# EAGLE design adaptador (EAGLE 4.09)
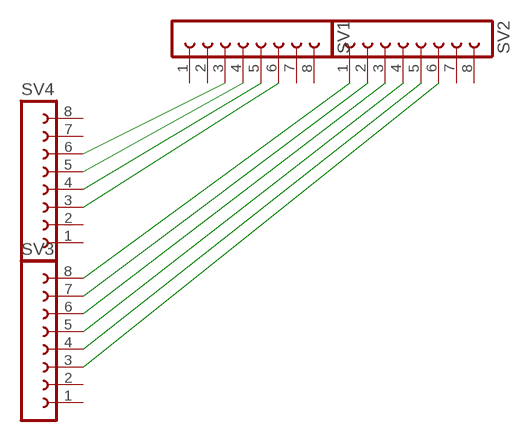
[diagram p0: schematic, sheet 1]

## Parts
SV1  FE08-1  [FE08]
SV2  FE08-1  [FE08]
SV3  FE08-1  [FE08]
SV4  FE08-1  [FE08]

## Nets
N$3: SV1.3 SV4.6
N$4: SV1.4 SV4.5
N$5: SV1.5 SV4.4
N$6: SV1.6 SV4.3
N$9: SV2.1 SV3.8
N$10: SV2.2 SV3.7
N$11: SV2.3 SV3.6
N$12: SV2.4 SV3.5
N$13: SV2.5 SV3.4
N$14: SV2.6 SV3.3
Unconnected: SV1.1 SV1.2 SV1.7 SV1.8 SV2.7 SV2.8 SV3.1 SV3.2 SV4.1 SV4.2 SV4.7 SV4.8

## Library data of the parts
SV1-SV4 = con-lsta:FE08-1: FEMALE HEADER

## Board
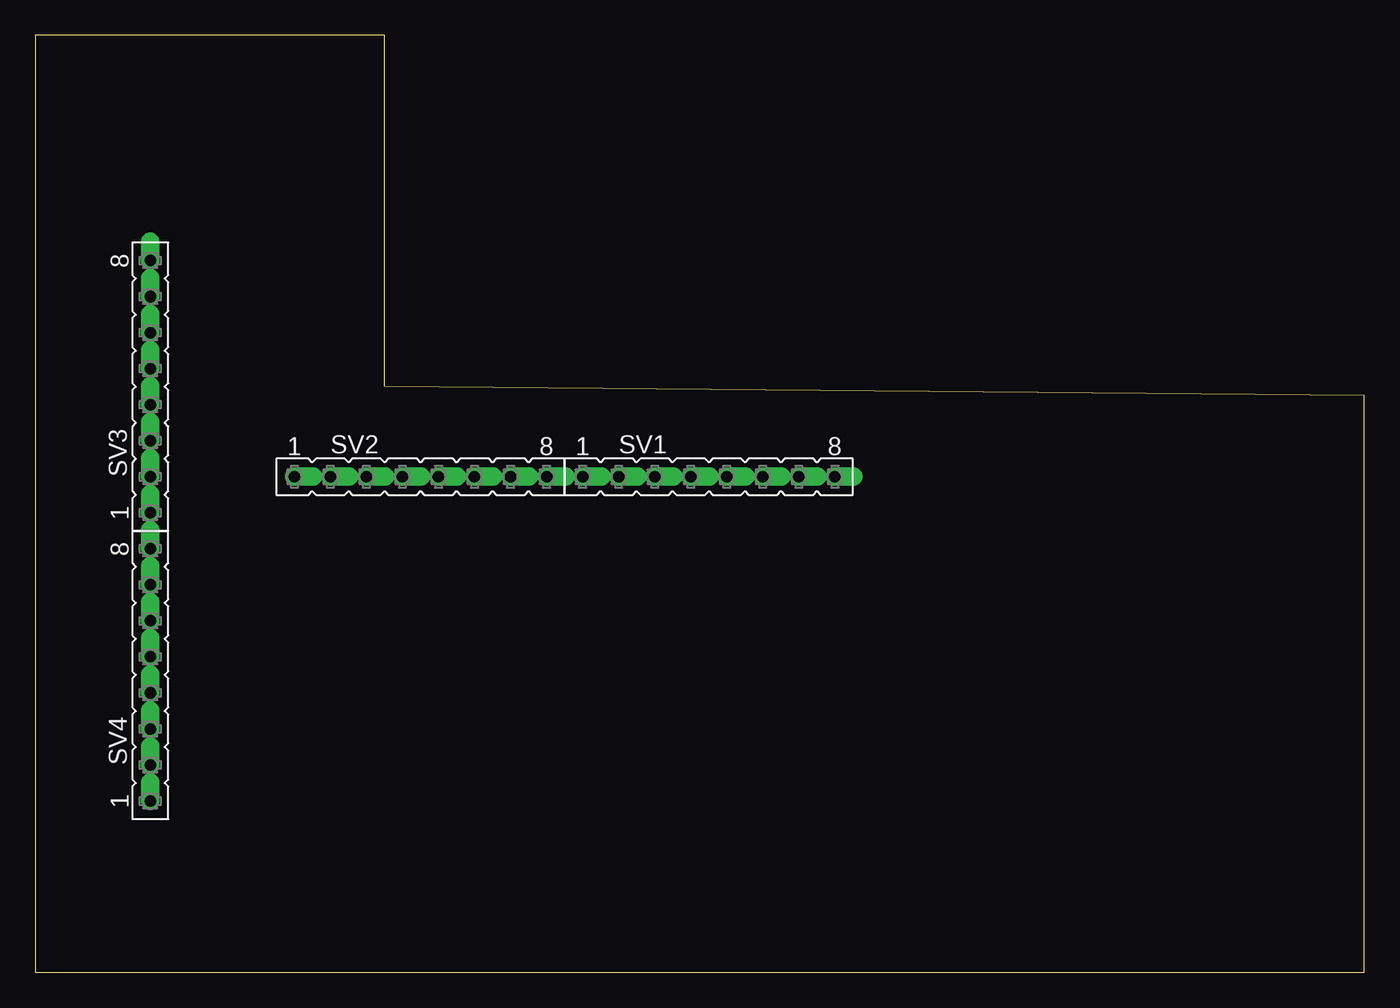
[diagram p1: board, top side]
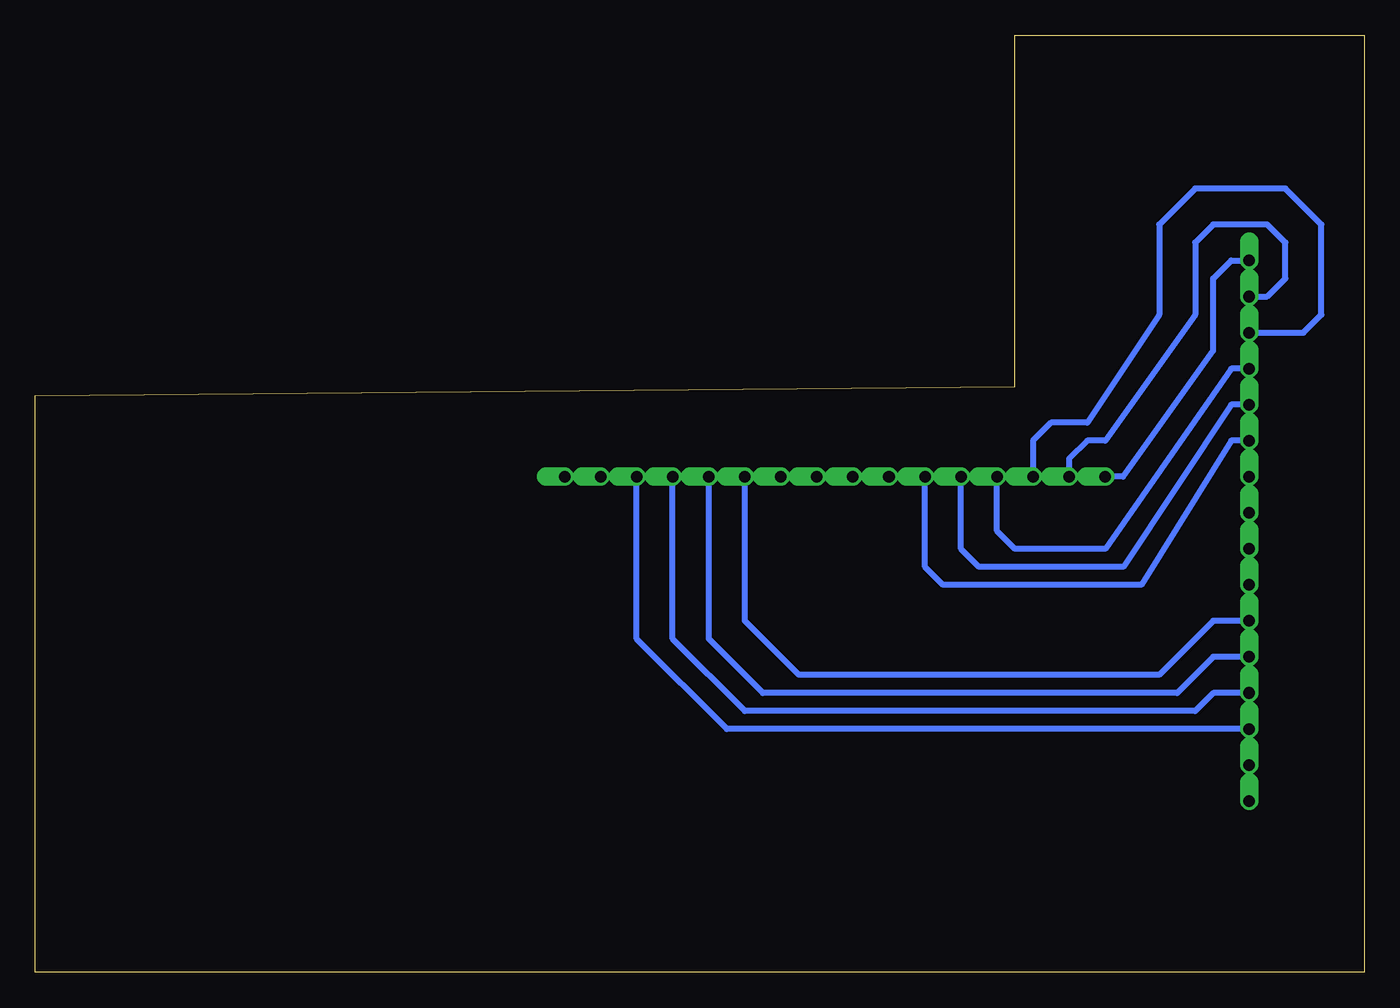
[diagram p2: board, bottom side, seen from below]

Size 93.65 x 66.03 mm. Coordinates in mm from the lower left corner, seen from the top.
Outline: 0,0 93.65,0 93.65,40.63 24.6,41.27 24.6,66.03 0,66.03 0,0
Copper layers used: Bottom

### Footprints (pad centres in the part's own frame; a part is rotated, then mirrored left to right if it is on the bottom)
FE08 = drill 0.813 offset: 1 -8.89,0; 2 -6.35,0; 3 -3.81,0; 4 -1.27,0; 5 1.27,0; 6 3.81,0; 7 6.35,0; 8 8.89,0

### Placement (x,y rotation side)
SV1  47.46,34.92 0 top
SV2  27.14,34.92 0 top
SV3  8.09,41.27 90 top
SV4  8.09,20.95 90 top

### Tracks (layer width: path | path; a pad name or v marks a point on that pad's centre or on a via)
N$3
  Bottom 0.406: SV4.6 10.63,24.76 14.44,20.95 39.84,20.95 43.65,24.76 SV1.3
N$4
  Bottom 0.406: SV4.5 10.63,22.22 13.17,19.68 42.38,19.68 46.19,23.49 SV1.4
N$5
  Bottom 0.406: SV4.4 10.63,19.68 11.9,18.41 43.65,18.41 48.73,23.49 SV1.5
N$6
  Bottom 0.406: SV4.3 44.92,17.14 51.27,23.49 SV1.6
N$9
  Bottom 0.406: SV3.8 9.36,50.16 10.63,48.89 10.63,43.81 16.98,34.92 SV2.1
N$10
  Bottom 0.406: SV3.7 6.82,47.62 5.55,48.89 5.55,51.43 6.82,52.7 10.63,52.7 11.9,51.43 11.9,46.35 18.25,37.46 19.52,37.46 20.79,36.19 SV2.2
N$11
  Bottom 0.406: SV3.6 4.28,45.08 3.01,46.35 3.01,52.7 5.55,55.24 11.9,55.24 14.44,52.7 14.44,46.35 19.52,38.73 22.06,38.73 23.33,37.46 SV2.3
N$12
  Bottom 0.406: SV2.4 25.87,31.11 24.6,29.84 18.25,29.84 9.36,42.54 SV3.5
N$13
  Bottom 0.406: SV2.5 28.41,29.84 27.14,28.57 16.98,28.57 9.36,40 SV3.4
N$14
  Bottom 0.406: SV3.3 9.36,37.46 15.71,27.3 29.68,27.3 30.95,28.57 SV2.6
